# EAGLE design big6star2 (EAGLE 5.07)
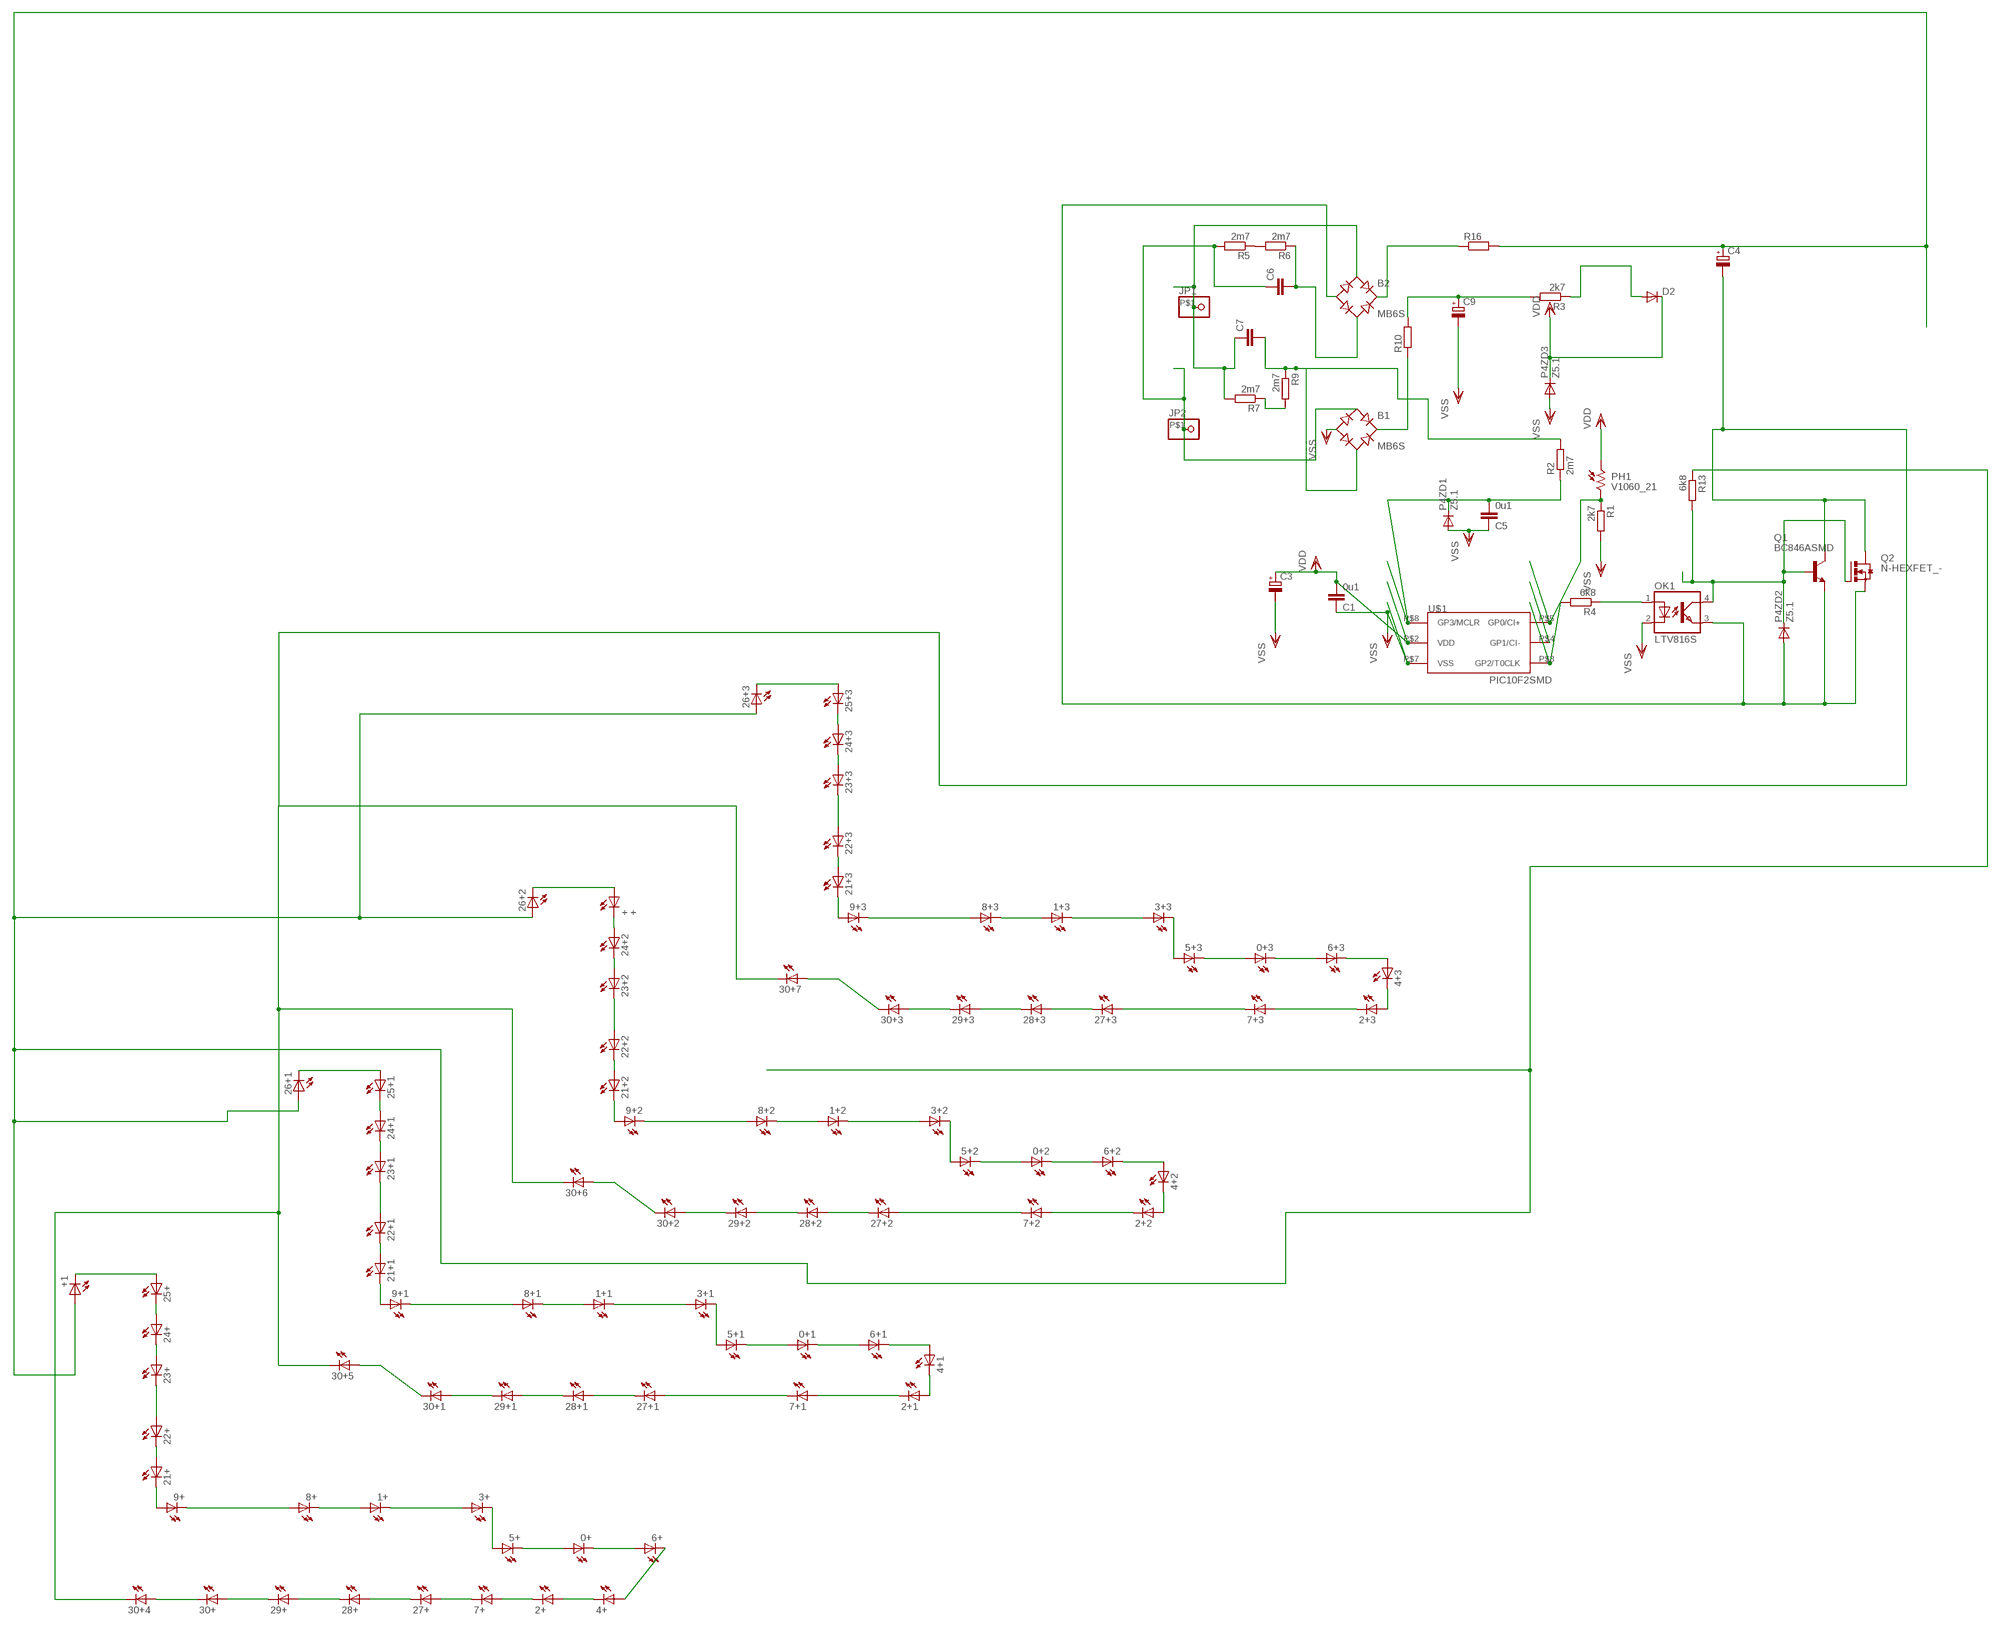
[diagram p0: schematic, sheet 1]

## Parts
0+  LED1210  [1210]
0+1  LED1210  [1210]
0+2  LED1210  [1210]
0+3  LED1210  [1210]
1+  LED1210  [1210]
1+1  LED1210  [1210]
1+2  LED1210  [1210]
1+3  LED1210  [1210]
2+  LED1210  [1210]
2+1  LED1210  [1210]
2+2  LED1210  [1210]
2+3  LED1210  [1210]
3+  LED1210  [1210]
3+1  LED1210  [1210]
3+2  LED1210  [1210]
3+3  LED1210  [1210]
4+  LED1210  [1210]
4+1  LED1210  [1210]
4+2  LED1210  [1210]
4+3  LED1210  [1210]
5+  LED1210  [1210]
5+1  LED1210  [1210]
5+2  LED1210  [1210]
5+3  LED1210  [1210]
6+  LED1210  [1210]
6+1  LED1210  [1210]
6+2  LED1210  [1210]
6+3  LED1210  [1210]
7+  LED1210  [1210]
7+1  LED1210  [1210]
7+2  LED1210  [1210]
7+3  LED1210  [1210]
8+  LED1210  [1210]
8+1  LED1210  [1210]
8+2  LED1210  [1210]
8+3  LED1210  [1210]
9+  LED1210  [1210]
9+1  LED1210  [1210]
9+2  LED1210  [1210]
9+3  LED1210  [1210]
21+  LED1210  [1210]
21+1  LED1210  [1210]
21+2  LED1210  [1210]
21+3  LED1210  [1210]
22+  LED1210  [1210]
22+1  LED1210  [1210]
22+2  LED1210  [1210]
22+3  LED1210  [1210]
23+  LED1210  [1210]
23+1  LED1210  [1210]
23+2  LED1210  [1210]
23+3  LED1210  [1210]
24+  LED1210  [1210]
24+1  LED1210  [1210]
24+2  LED1210  [1210]
24+3  LED1210  [1210]
25+  LED1210  [1210]
25+1  LED1210  [1210]
25+3  LED1210  [1210]
26+1  LED1210  [1210]
26+2  LED1210  [1210]
26+3  LED1210  [1210]
27+  LED1210  [1210]
27+1  LED1210  [1210]
27+2  LED1210  [1210]
27+3  LED1210  [1210]
28+  LED1210  [1210]
28+1  LED1210  [1210]
28+2  LED1210  [1210]
28+3  LED1210  [1210]
29+  LED1210  [1210]
29+1  LED1210  [1210]
29+2  LED1210  [1210]
29+3  LED1210  [1210]
30+  LED1210  [1210]
30+1  LED1210  [1210]
30+2  LED1210  [1210]
30+3  LED1210  [1210]
30+4  LED1210  [1210]
30+5  LED1210  [1210]
30+6  LED1210  [1210]
30+7  LED1210  [1210]
+  +  LED1210  [1210]
+1  LED1210  [1210]
B1  MB6S  [SOIC-4]
B2  MB6S  [SOIC-4]
C1  0u1  C-EUC1206  [C1206]
C3  CPOL-EUD  [PANASONIC_D]
C4  CPOL-EUSANYO_SMD_F12  [SANYO-OSCON_SMD_F12]
C5  0u1  C-EUC1206  [C1206]
C6  C-EUSMD200  [SMD200]
C7  C-EUSMD100  [SMD100]
C9  CPOL-EUD  [PANASONIC_D]
D2  DIODE-MINIMELF  [MINIMELF]
JP1  PINHD-1X1SMD  [SMD1X1]
JP2  PINHD-1X1SMD  [SMD1X1]
OK1  LTV816S  [SMD4]
P4ZD1  Z5.1  DIODE-MINIMELF  [MINIMELF]
P4ZD2  Z5.1  DIODE-MINIMELF  [MINIMELF]
P4ZD3  Z5.1  DIODE-MINIMELF  [MINIMELF]
PH1  V1060_21  [TO-5_V10]
Q1  BC846ASMD  [SOT23]
Q2  N-HEXFET_-  [TO252]
R1  2k7  R-EU_R1206  [R1206]
R2  2m7  R-EU_R1206  [R1206]
R3  2k7  R-EU_R1206  [R1206]
R4  6k8  R-EU_R1206  [R1206]
R5  2m7  R-EU_R1210  [R1210]
R6  2m7  R-EU_R1210  [R1210]
R7  2m7  R-EU_R1210  [R1210]
R9  2m7  R-EU_R1210  [R1210]
R10  R-EU_SMD15  [SMDCARB15]
R13  6k8  R-EU_R1206  [R1206]
R16  R-EU_SMD15  [SMDCARB15]
U$1  PIC10F2SMD  [DIL8SMD]

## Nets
AC1: B1.~1(AC1) C6.P$1 JP2.P$1 R5.2
AC2: B2.~1(AC1) C7.P$1 JP1.P$1 R7.2
CBIG: B2.~2(AC2) C6.P$2 R6.1
CSMALL: B1.~2(AC2) C7.P$2 R2.2 R9.1
D+: 26+1.P$1(A) 26+2.P$1(A) 26+3.P$1(A) +1.P$1(A) C4.+ R13.1 R16.P$2
DR+: C9.+ R3.2 R10.P$2
MINUS: 30+4.P$2(C) 30+5.P$2(C) 30+6.P$2(C) 30+7.P$2(C) C4.- Q1.3(C) Q2.3(D)
N$1: 30+3.P$2(C) 30+7.P$1(A)
N$2: 30+2.P$2(C) 30+6.P$1(A)
N$4: 30+1.P$2(C) 30+5.P$1(A)
N$5: 30+4.P$1(A) 30+.P$2(C)
N$6: 8+.P$1(A) 9+.P$2(C)
N$7: 29+.P$2(C) 30+.P$1(A)
N$8: 28+.P$2(C) 29+.P$1(A)
N$9: 27+.P$2(C) 28+.P$1(A)
N$10: 29+1.P$2(C) 30+1.P$1(A)
N$11: 28+1.P$2(C) 29+1.P$1(A)
N$12: 2+.P$2(C) 7+.P$1(A)
N$13: 7+.P$2(C) 27+.P$1(A)
N$14: 2+.P$1(A) 4+.P$2(C)
N$15: 4+.P$1(A) 6+.P$2(C)
N$16: 0+.P$2(C) 6+.P$1(A)
N$17: 0+.P$1(A) 5+.P$2(C)
N$18: 3+.P$2(C) 5+.P$1(A)
N$19: 1+.P$2(C) 3+.P$1(A)
N$20: 1+.P$1(A) 8+.P$2(C)
N$21: 27+1.P$2(C) 28+1.P$1(A)
N$22: 2+1.P$1(A) 4+1.P$2(C)
N$23: 9+.P$1(A) 21+.P$2(C)
N$24: 21+.P$1(A) 22+.P$2(C)
N$25: 22+.P$1(A) 23+.P$2(C)
N$26: 24+.P$1(A) 25+.P$2(C)
N$27: 25+.P$1(A) +1.P$2(C)
N$28: 23+.P$1(A) 24+.P$2(C)
N$29: 4+1.P$1(A) 6+1.P$2(C)
N$30: 0+1.P$2(C) 6+1.P$1(A)
N$31: 0+1.P$1(A) 5+1.P$2(C)
N$32: 3+1.P$2(C) 5+1.P$1(A)
N$33: 1+1.P$2(C) 3+1.P$1(A)
N$34: 1+1.P$1(A) 8+1.P$2(C)
N$35: 9+1.P$1(A) 21+1.P$2(C)
N$36: 21+1.P$1(A) 22+1.P$2(C)
N$37: 22+1.P$1(A) 23+1.P$2(C)
N$38: 25+1.P$1(A) 26+1.P$2(C)
N$39: 24+1.P$1(A) 25+1.P$2(C)
N$40: 23+1.P$1(A) 24+1.P$2(C)
N$41: 2+1.P$2(C) 7+1.P$1(A)
N$42: 7+1.P$2(C) 27+1.P$1(A)
N$43: 8+1.P$1(A) 9+1.P$2(C)
N$46: 29+2.P$2(C) 30+2.P$1(A)
N$47: 28+2.P$2(C) 29+2.P$1(A)
N$48: 27+2.P$2(C) 28+2.P$1(A)
N$49: 2+2.P$1(A) 4+2.P$2(C)
N$50: 4+2.P$1(A) 6+2.P$2(C)
N$51: 0+2.P$2(C) 6+2.P$1(A)
N$52: 0+2.P$1(A) 5+2.P$2(C)
N$53: 3+2.P$2(C) 5+2.P$1(A)
N$54: 1+2.P$2(C) 3+2.P$1(A)
N$55: 1+2.P$1(A) 8+2.P$2(C)
N$56: 9+2.P$1(A) 21+2.P$2(C)
N$57: 21+2.P$1(A) 22+2.P$2(C)
N$58: 22+2.P$1(A) 23+2.P$2(C)
N$59: 26+2.P$2(C) +.P$1(A)
N$60: 24+2.P$1(A) +.P$2(C)
N$61: 23+2.P$1(A) 24+2.P$2(C)
N$62: 2+2.P$2(C) 7+2.P$1(A)
N$63: 7+2.P$2(C) 27+2.P$1(A)
N$64: 8+2.P$1(A) 9+2.P$2(C)
N$67: 29+3.P$2(C) 30+3.P$1(A)
N$68: 28+3.P$2(C) 29+3.P$1(A)
N$69: 27+3.P$2(C) 28+3.P$1(A)
N$70: 2+3.P$1(A) 4+3.P$2(C)
N$71: 4+3.P$1(A) 6+3.P$2(C)
N$72: 0+3.P$2(C) 6+3.P$1(A)
N$73: 0+3.P$1(A) 5+3.P$2(C)
N$74: 3+3.P$2(C) 5+3.P$1(A)
N$75: 1+3.P$2(C) 3+3.P$1(A)
N$76: 1+3.P$1(A) 8+3.P$2(C)
N$77: 9+3.P$1(A) 21+3.P$2(C)
N$78: 21+3.P$1(A) 22+3.P$2(C)
N$79: 22+3.P$1(A) 23+3.P$2(C)
N$80: 25+3.P$1(A) 26+3.P$2(C)
N$81: 24+3.P$1(A) 25+3.P$2(C)
N$82: 23+3.P$1(A) 24+3.P$2(C)
N$83: 2+3.P$2(C) 7+3.P$1(A)
N$84: 7+3.P$2(C) 27+3.P$1(A)
N$85: 8+3.P$1(A) 9+3.P$2(C)
N$86: C5.2 P4ZD1.C R2.1 U$1.P$8(GP3/MCLR)
N$87: OK1.1(A) R4.1
N$88: PH1.2 R1.1 U$1.P$5(GP0/CI+)
N$89: R5.1 R6.2
N$90: R7.1 R9.2
N$91: B2.+ R16.P$1
N$92: D2.A R3.1
N$93: B2.- OK1.3(EMIT) P4ZD2.A Q1.2(E) Q2.2(S)
N$94: OK1.4(COL) P4ZD2.C Q1.1(B) Q2.1(G) R13.2
N$95: R4.2 U$1.P$3(GP2/T0CLK)
N$102: U$1.P$4(GP1/CI-)
RECDR+: B1.+ R10.P$1
VDD: C1.2 C3.+ D2.C P4ZD3.C PH1.1 U$1.P$2(VDD)
VSS: B1.- C1.1 C3.- C5.1 C9.- OK1.2(C) P4ZD1.A P4ZD3.A R1.2 U$1.P$7(VSS)

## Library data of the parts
0+ 0+1-0+3 1+ 1+1-1+3 2+ 2+1-2+3 3+ 3+1-3+3 4+ 4+1-4+3 5+ 5+1-5+3 6+ 6+1-6+3 7+ 7+1-7+3 8+ 8+1-8+3 9+ 9+1-9+3 21+ 21+1-21+3 22+ 22+1-22+3 23+ 23+1-23+3 24+ 24+1-24+3 25+ 25+1 25+3 26+1-26+3 27+ 27+1-27+3 28+ 28+1-28+3 29+ 29+1-29+3 30+ 30+1-30+7 + +1 = led(2):LED: LED
B1 B2 = rectifier:MB*S: Bridge Rectifier Source: http://www.fairchildsemi.com/ds/MB/MB6S.pdf
C1 C5-C7 = rcl:C-EU: CAPACITOR, European symbol
C3 C4 C9 = rcl-2:CPOL-EU: POLARIZED CAPACITOR, European symbol
D2 P4ZD1-P4ZD3 = diode:DIODE-: DIODE
JP1 JP2 = pinhead:PINHD-1X1: PIN HEADER
OK1 = optocoupler:LTV816: OPTO COUPLER Source: LITEON, LTV816.pdf
PH1 = photo-elements:?1060*: Sensor Street Light control
Q1 = transistor-npn:BC846*: NPN Transistor
Q2 = transistor-power:N-HEXFET_?-*: HEXFET® Power MOSFET
R1-R7 R9 R13 = rcl-2:R-EU_: RESISTOR, European symbol
R10 R16 = rcl:R-EU_: RESISTOR, European symbol
U$1 = microchip-5:PIC10F2*: uPC nW 0,25/0,5k Program Flash memory Comparator

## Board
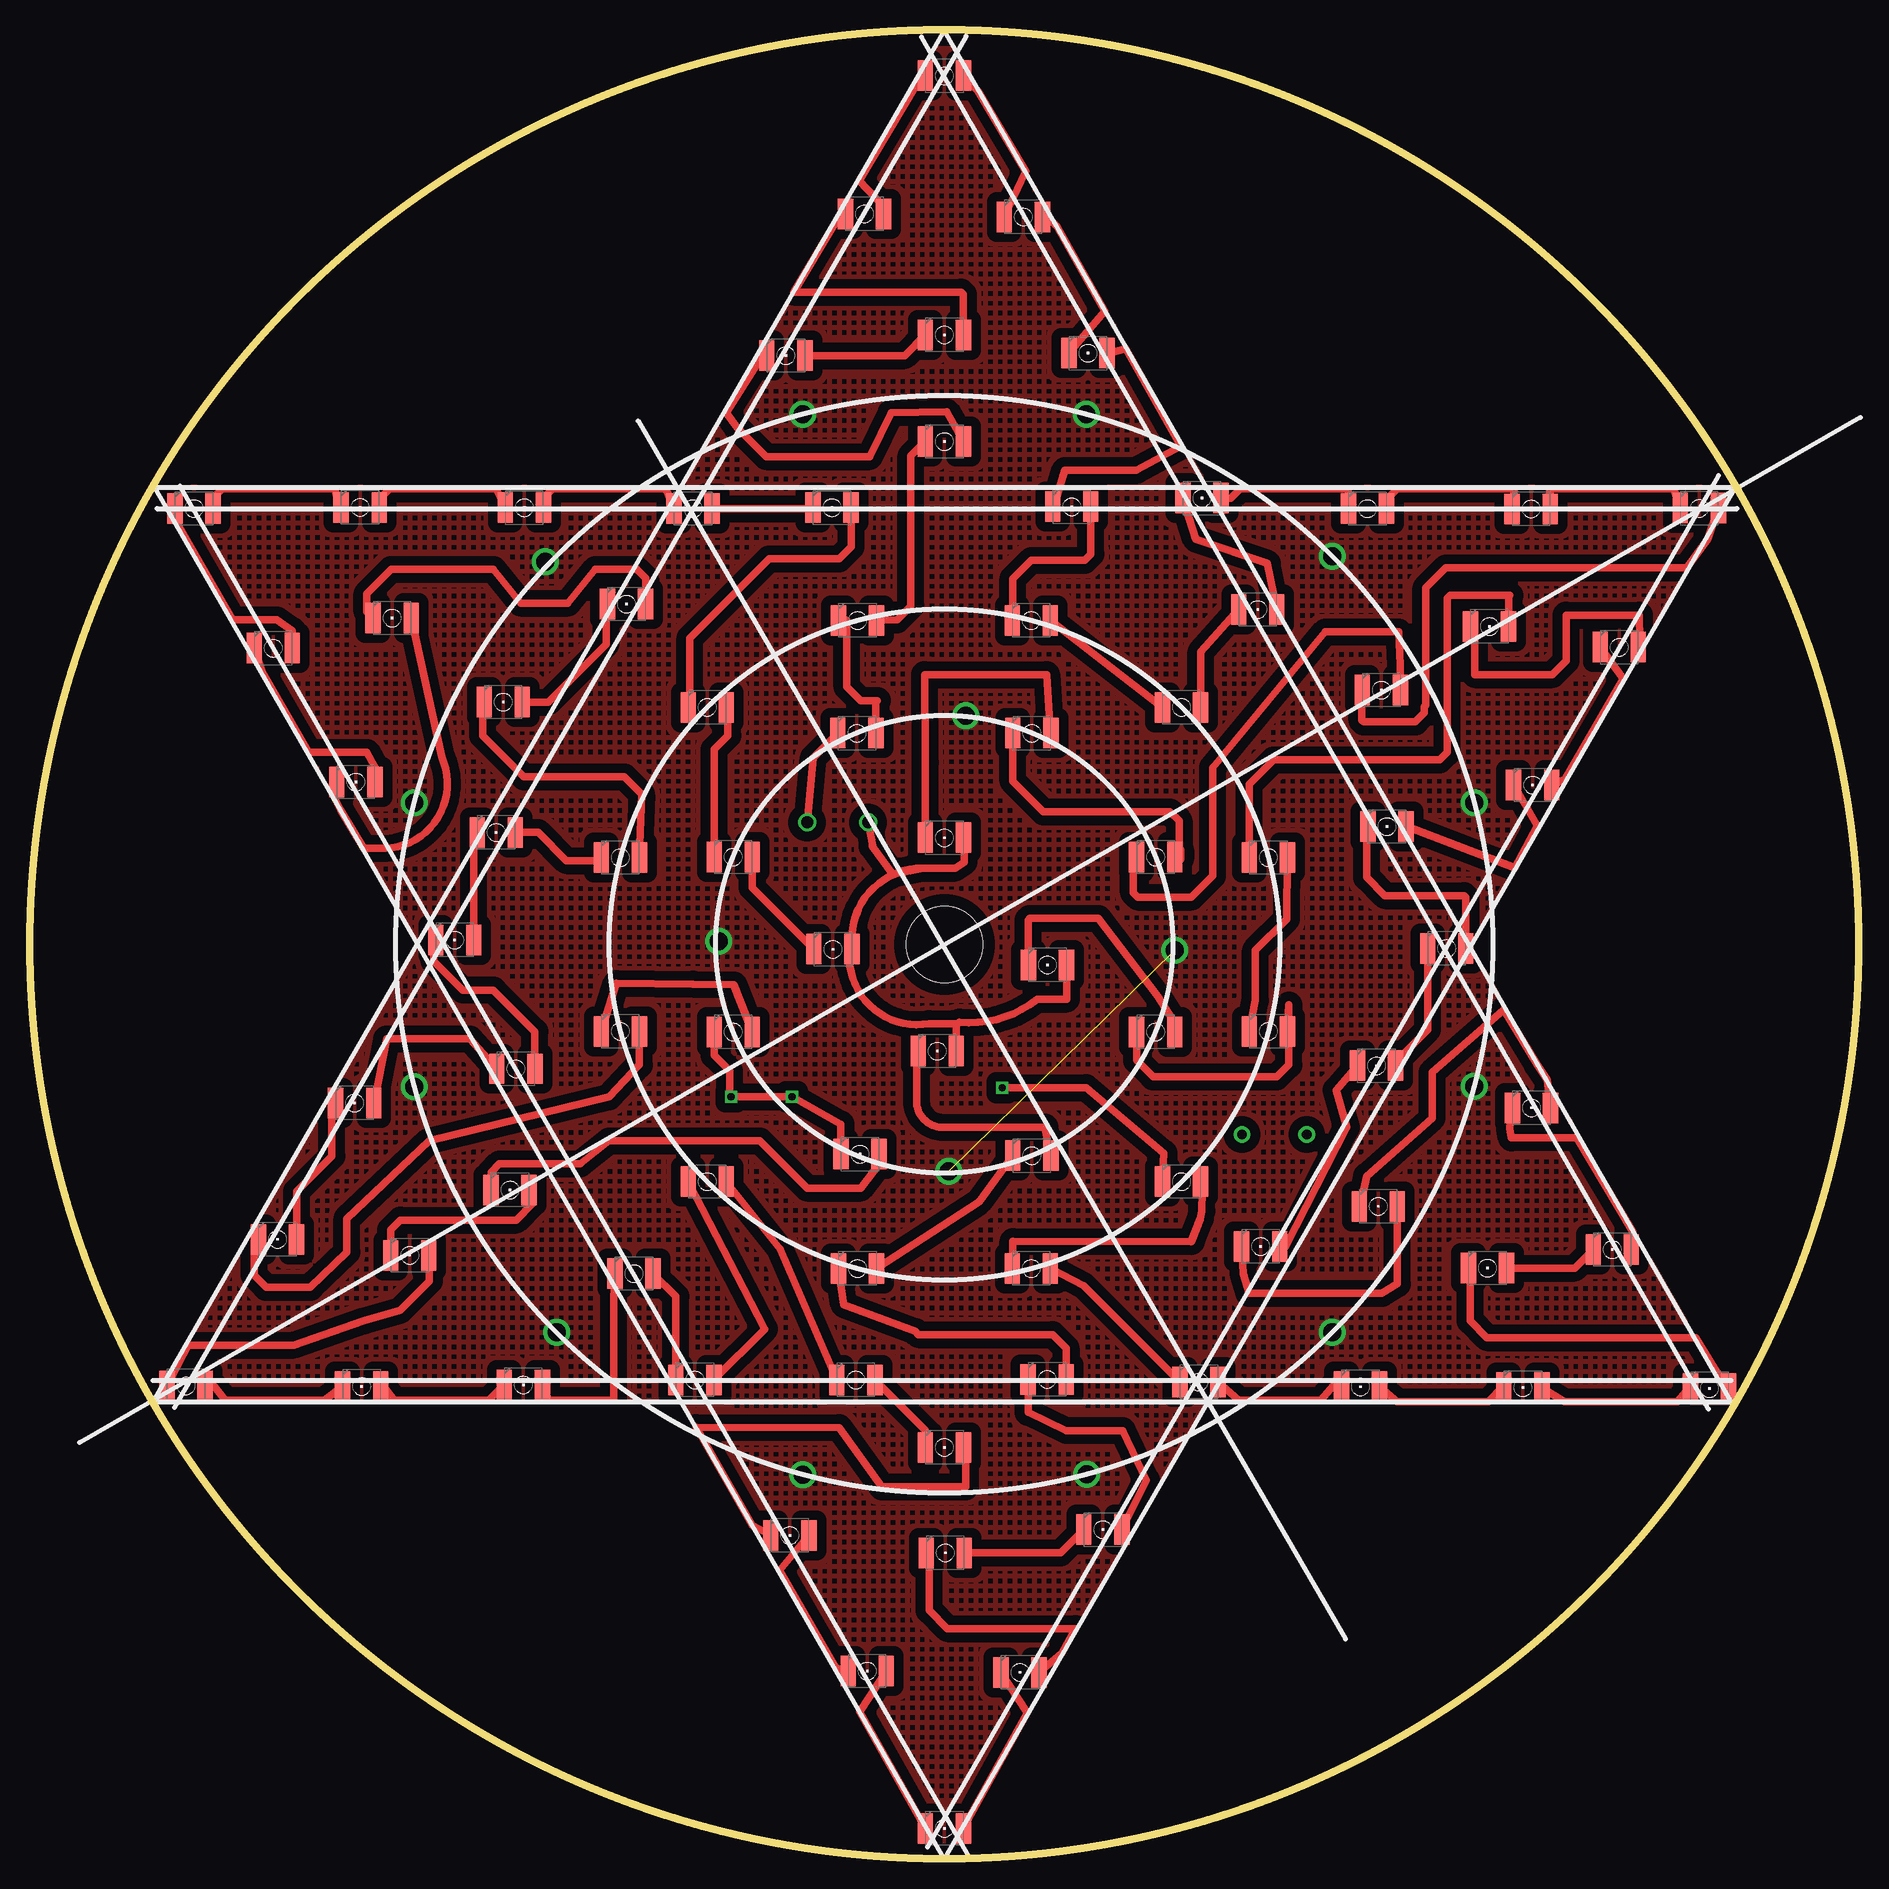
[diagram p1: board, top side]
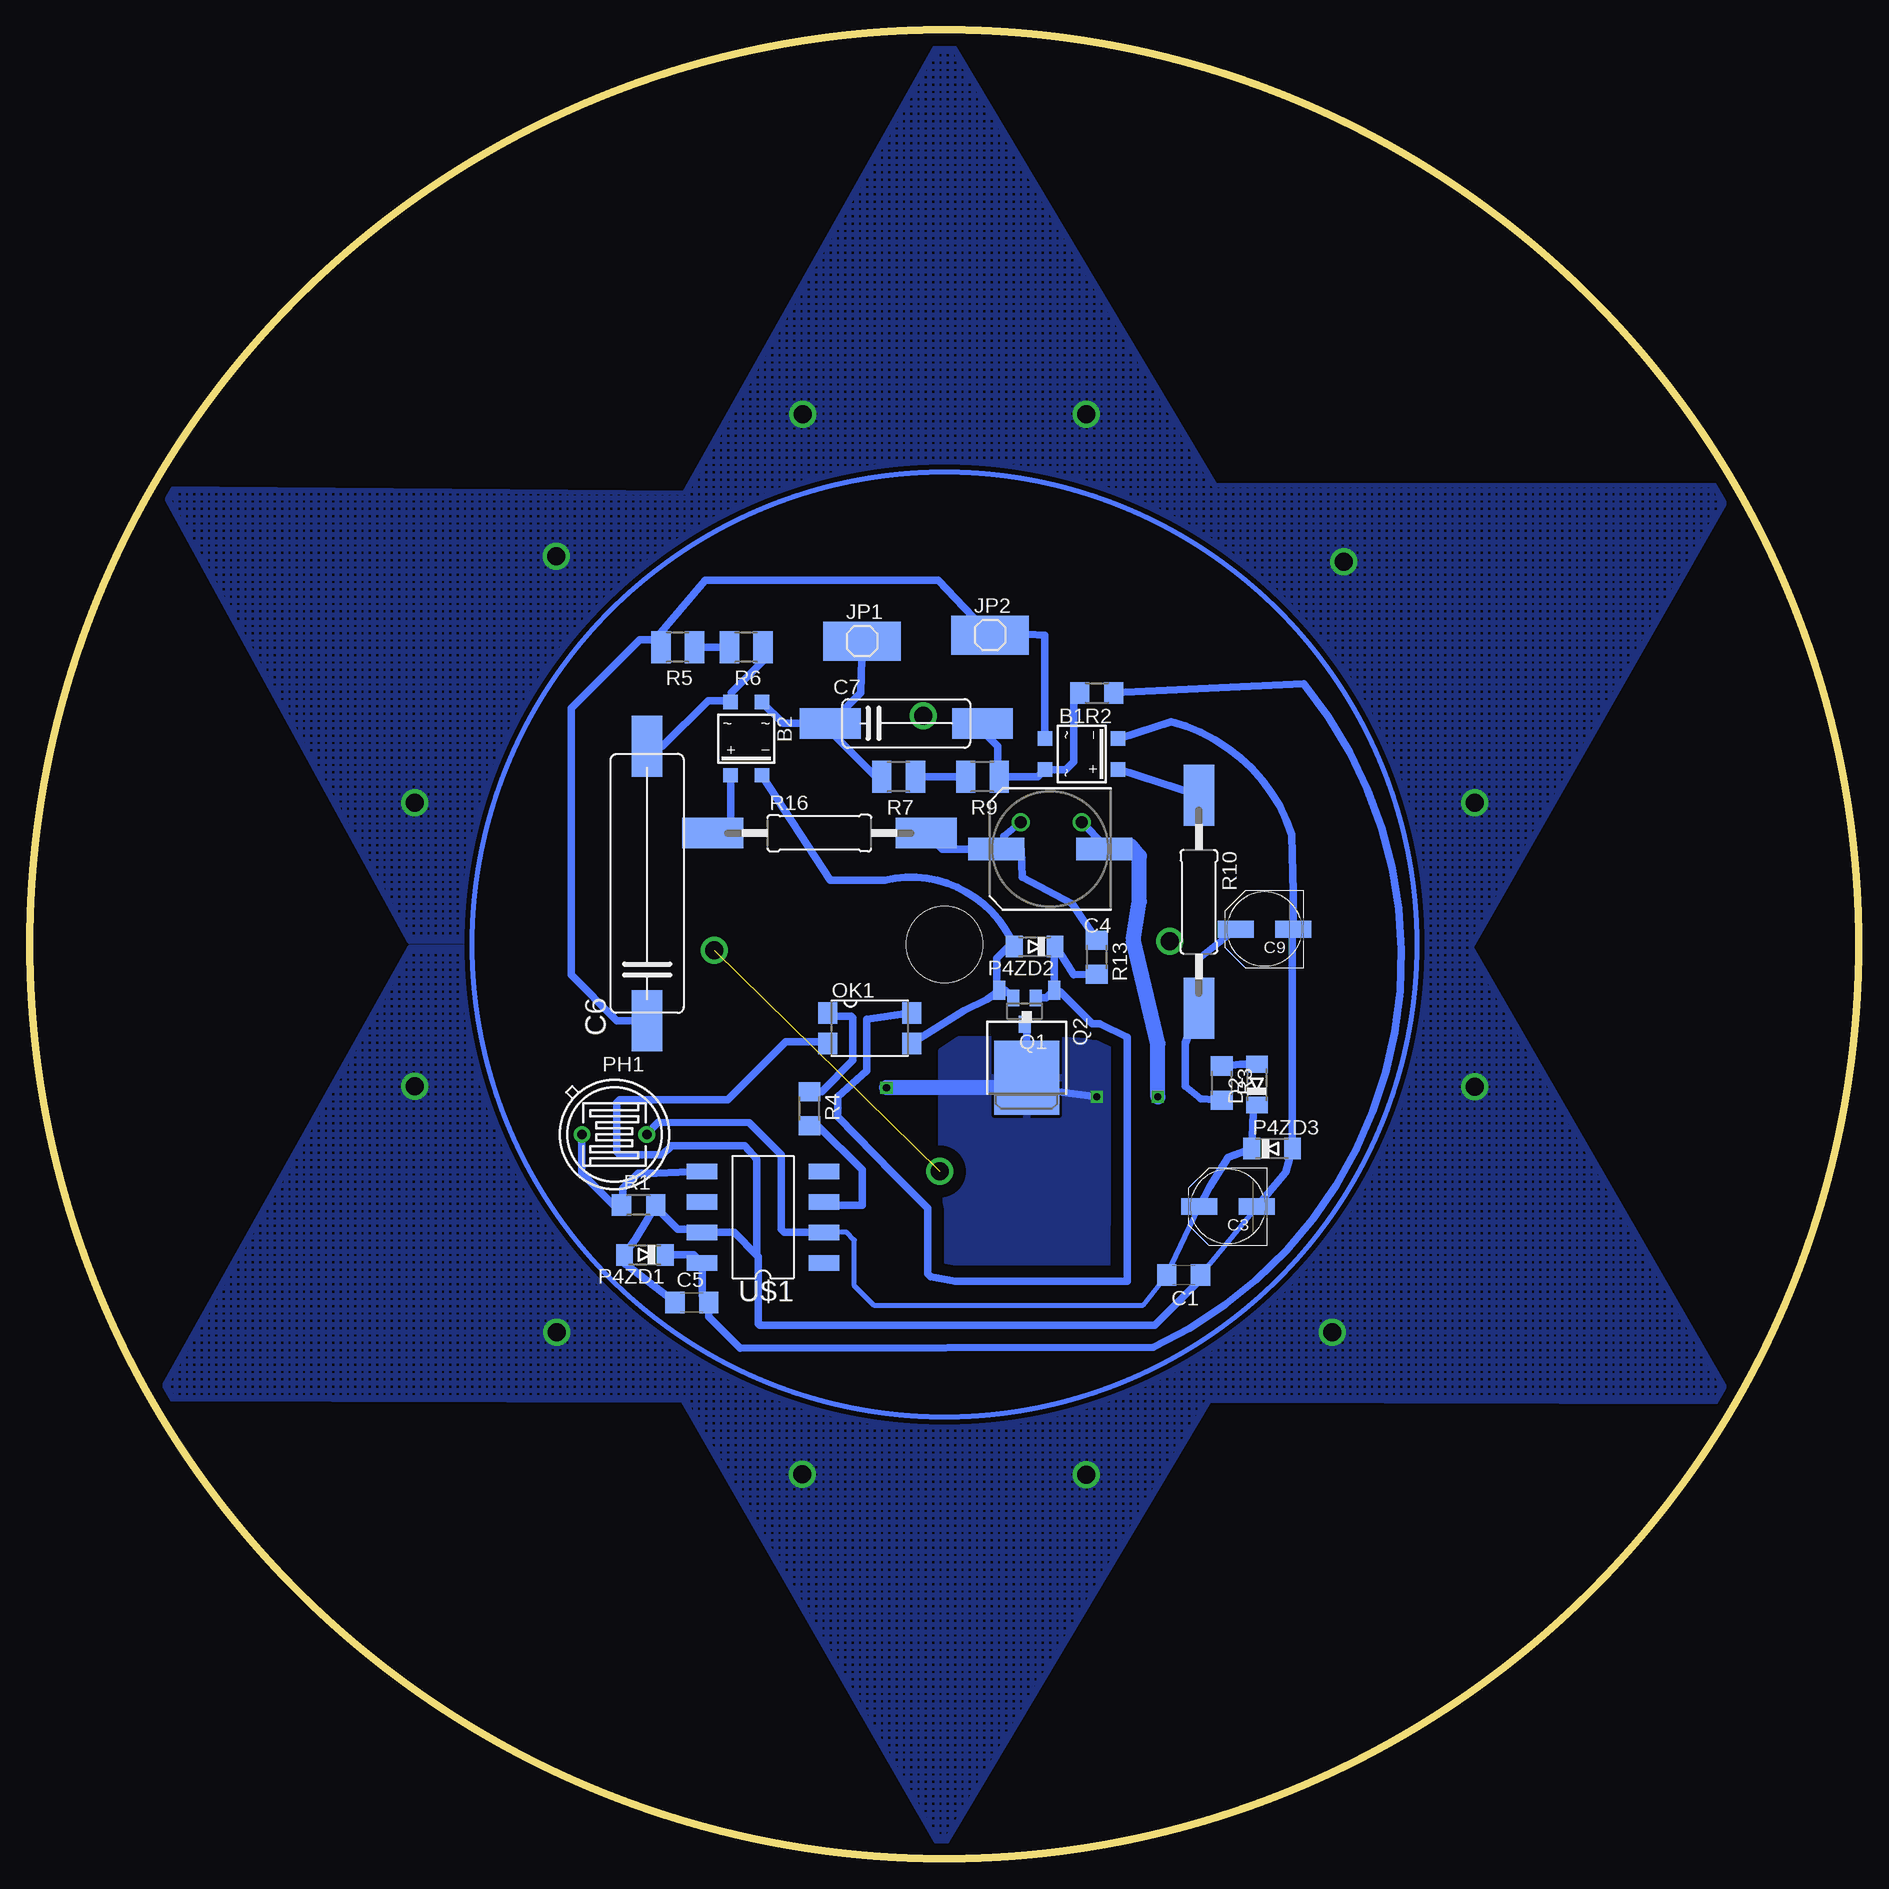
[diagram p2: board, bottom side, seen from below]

Size 152.4 x 152.4 mm. Coordinates in mm from the lower left corner, seen from the top.
Outline: circle at 76.2,76.2 radius 76.2
Copper layers (1*16): Top 0.035mm / dielectric 1.5mm / Bottom 0.035mm
Design rules "default": minimum track width 10mil, minimum drill 24mil, track to track 8mil, track to pad 8mil, pad to pad 8mil, via to via 8mil, smd to smd 8mil, copper to edge 40mil, drill to drill 8mil, minimum pad ring 10mil, minimum via ring 8mil, stop-mask expansion 4mil, vias tented up to drill 0mil, thermal gap 10mil
Holes 6.35 mm at 76.2,76.2

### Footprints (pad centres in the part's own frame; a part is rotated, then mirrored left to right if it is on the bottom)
1210 = smd 1.27 x 2.54: P$1 1.587,0; P$2 -1.587,0
SOIC-4 = smd 1.2 x 1.2: + 1.3,3.05; - -1.3,3.05; ~1 -1.3,-3.05; ~2 1.3,-3.05
C1206 = smd 1.6 x 1.8: 1 -1.4,0; 2 1.4,0
PANASONIC_D = smd 3 x 1.4: + 2.4,0; - -2.4,0
SANYO-OSCON_SMD_F12 = smd 4.7 x 1.9: + 4.5,0; - -4.5,0
SMD200 = smd 5.08 x 2.54: P$1 -10.16,0; P$2 12.7,0
SMD100 = smd 5.08 x 2.54: P$1 -6.35,0; P$2 6.35,0
MINIMELF = smd 1.4 x 1.8: A 1.7,0; C -1.7,0
SMD1X1 = smd 6.452 x 3.251: P$1 0,0
SMD4 = smd 1.78 x 1.55: 1 -1.27,-3.5; 2 1.27,-3.5; 3 1.27,3.5; 4 -1.27,3.5
TO-5_V10 = drill 0.8 pad 1.4 round: 1 -2.7,0; 2 2.7,0
SOT23 = smd 1 x 1.4: 1 -0.95,-1.1; 2 0.95,-1.1; 3 0,1.1
TO252 = smd 1 x 1.6: 1 -2.28,-3.53; 2 2.28,-3.53 | smd 5.4 x 6.2: 3 0,3.77
R1206 = smd 1.6 x 1.803: 1 -1.422,0; 2 1.422,0
R1210 = smd 1.6 x 2.7: 1 -1.4,0; 2 1.4,0
SMDCARB15 = smd 5.08 x 2.54: P$1 -8.89,0; P$2 8.89,0
DIL8SMD = smd 1.27 x 2.54: P$1 -3.81,-5.08; P$2 -1.27,-5.08; P$3 1.27,-5.08; P$4 3.81,-5.08; P$5 3.81,5.08; P$6 1.27,5.08; P$7 -1.27,5.08; P$8 -3.81,5.08

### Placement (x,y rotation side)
0+  68.82,39.91 0 top
0+1  112.36,54.38 0 top
0+2  86.82,112.67 0 top
0+3  49.71,104.56 0 top
1+  69.77,15.65 0 top
1+1  118.06,75.87 0 top
1+2  102.31,104.11 0 top
1+3  20.28,100.89 0 top
2+  50.33,48.77 0 top
2+1  121.46,49.23 0 top
2+2  76.2,148.59 0 top
2+3  38.85,85.54 0 top
3+  63.32,26.95 0 top
3+1  112.21,66.09 0 top
3+2  95.96,95.96 0 top
3+3  27.15,89.74 0 top
4+  55.41,39.91 0 top
4+1  131.85,50.77 0 top
4+2  82.78,136.83 0 top
4+3  49.2,83.44 0 top
5+  76.2,34.29 0 top
5+1  102.56,51.04 0 top
5+2  83.44,103.2 0 top
5+3  30.18,103.4 0 top
6+  56.44,56.44 0 top
6+1  125.12,62.59 0 top
6+2  88.16,125.48 0 top
6+3  39.43,96.4 0 top
7+  41.11,39.5 0 top
7+1  139.95,39.19 0 top
7+2  69.55,137.08 0 top
7+3  35.39,76.57 0 top
8+  76.2,2.54 0 top
8+1  113.08,86.03 0 top
8+2  97.66,113.39 0 top
8+3  13.67,112.53 0 top
9+  82.5,15.54 0 top
9+1  125.22,89.48 0 top
9+2  111.46,112.52 0 top
9+3  27.51,112.62 0 top
21+  76.28,25.5 0 top
21+1  132.44,100.97 0 top
21+2  125.09,112.5 0 top
21+3  41.2,112.6 0 top
22+  89.41,27.43 0 top
22+1  121.63,102.7 0 top
22+2  139.12,112.55 0 top
22+3  55.25,112.52 0 top
23+  84.76,39.96 0 top
23+1  103.2,83.44 0 top
23+2  112.62,97.4 0 top
23+3  66.84,112.6 0 top
24+  68.96,49.2 0 top
24+1  103.2,68.96 0 top
24+2  93.8,83.49 0 top
24+3  56.44,95.96 0 top
25+  83.49,58.6 0 top
25+1  93.8,68.91 0 top
25+3  58.6,83.49 0 top
26+1  84.79,74.5 0 top
26+2  76.2,85.09 0 top
26+3  66.91,75.8 0 top
27+  27.64,39.37 0 top
27+1  124.41,39.27 0 top
27+2  76.2,127 0 top
27+3  40.49,65.84 0 top
28+  13,39.42 0 top
28+1  110.87,39.34 0 top
28+2  62.99,125.27 0 top
28+3  27.05,62.99 0 top
29+  31.65,50.29 0 top
29+1  97.41,39.74 0 top
29+2  76.2,118.11 0 top
29+3  20.63,51.63 0 top
30+  40.01,55.74 0 top
30+1  83.44,49.2 0 top
30+2  68.96,103.2 0 top
30+3  49.2,68.96 0 top
30+4  69.16,58.72 0 top
30+5  95.96,56.44 0 top
30+6  68.91,93.8 0 top
30+7  58.6,68.91 0 top
+  83.49,93.8 0 top
+1  75.6,67.31 0 top
B1  64.77,92.08 270 bottom
B2  92.71,93.34 180 bottom
C1  56.26,48.64 180 bottom
C3  52.58,54.36 180 bottom
C4  67.38,84.14 180 bottom
C5  97.25,46.36 0 bottom
C6  100.97,80.01 90 bottom
C7  79.38,94.61 0 bottom
C9  49.53,77.47 180 bottom
D2  50.16,64.52 90 bottom
JP1  83.06,101.47 0 bottom
JP2  72.39,101.98 0 bottom
OK1  82.42,69.22 270 bottom
P4ZD1  101.16,50.33 180 bottom
P4ZD2  68.68,76.02 180 bottom
P4ZD3  48.9,59.18 0 bottom
PH1  103.69,60.36 180 bottom
Q1  69.52,70.64 180 bottom
Q2  69.34,68.86 180 bottom
R1  101.69,54.48 0 bottom
R2  63.5,97.16 180 bottom
R3  53.09,64.64 270 bottom
R4  87.45,62.51 270 bottom
R5  98.42,100.97 180 bottom
R6  92.71,100.97 180 bottom
R7  80.01,90.17 180 bottom
R9  73.03,90.17 180 bottom
R10  54.99,79.76 270 bottom
R13  63.5,75.13 270 bottom
R16  86.61,85.47 0 bottom
U$1  91.31,53.47 90 bottom

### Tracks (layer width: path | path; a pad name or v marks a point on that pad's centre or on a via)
AC1
  Bottom 0.61: B1.~1 67.82,101.98 69.98,102.11 JP2.P$1 76.71,106.55 96.14,106.55 100.33,101.6 | 100.33,101.6 100.33,101.47 R5.2 | C6.P$1 103.5,69.85 107.31,73.66 107.31,95.89 101.6,101.6 100.33,101.6
AC2
  Bottom 0.61: R7.2 81.92,90.17 86.36,94.61 C7.P$1 | JP1.P$1 83.19,97.16 C7.P$1 | C7.P$1 89.63,94.61 B2.~1
CBIG
  Bottom 0.61: R6.1 91.31,99.83 93.98,97.16 93.98,96.42 B2.~2 94.14,96.52 95.89,96.52 99.69,92.71 C6.P$2
CSMALL
  Bottom 0.61: R2.2 65.41,96.67 65.41,91.44 66.07,90.78 B1.~2 68.42,90.17 R9.1 71.75,90.3 71.75,92.71 73.03,93.98 C7.P$2
D+  (via drill 1 pad 1.27)
  Top 0.61: 74.42,82.55 arc94 68.5,76.37 26+3.P$1 68.33,75.63 68.33,74.42 arc93 74.93,69.6 76.96,69.6 77.31,69.62 77.19,69.47 | 74.42,82.55 77.09,82.55 77.85,83.06 77.85,85.03 26+2.P$1 | 77.19,69.47 +1.P$1 | 26+1.P$1 86.38,71.64 83.95,71.63 arc-44 77.44,69.72 77.19,69.47 | 74.42,82.55 71.88,82.04 70.18,84.38 70.23,84.42 v69.85,86.36
  Bottom 0.61: R13.1 65.53,79.6 69.72,81.79 69.79,84.14 71.25,84.14 | 71.25,84.14 C4.+ 76.39,84.14 R16.P$2 | v69.85,86.36 71.25,85.22 71.25,84.14
DR+
  Bottom 0.61: R3.2 54.84,63.35 56.13,64.39 56.13,67.94 R10.P$2 54.98,75.06 C9.+
MINUS  (via drill 0.6, 1 pad 1.27)
  Top 0.61: 30+6.P$2 65.28,91.76 v64.77,86.36 | 30+5.P$2 94.49,58.8 88.01,64.26 v81.03,64.26 | 30+4.P$2 67.58,61.23 v63.5,63.5 v58.42,63.5 58.29,63.5 58.29,65.66 57.01,66.94 30+7.P$2
  Bottom 0.61: 60.64,84.4 C4.- 62.88,84.47 v64.77,86.36 | Q2.3 70.17,64.26 | v63.5,63.5 68.39,64.14 Q2.3 | Q1.3 69.34,69.54 Q2.3
  Bottom 1.27: 60.64,84.4 59.94,83.57 59.94,79.76 60.45,76.58 58.42,67.94 v58.42,63.5 | 70.17,64.26 v81.03,64.26
  pour Bottom (isolate 1.016): 67.18,68.25 74.98,68.25 76.41,67.31 76.41,49.48 62.66,49.33 62.64,56.21 62.64,68.02
N$1
  Top 0.61: 30+3.P$2 48.87,72.95 55.24,72.9 58.66,72.82 30+7.P$1
N$2
  Top 0.61: 30+2.P$2 68.07,103.21 68.07,97.66 69.22,96.52 70.61,96.52 70.5,96.41 30+6.P$1
N$4
  Top 0.61: 30+1.P$2 81.92,51.45 96.77,51.44 97.54,53.34 97.66,53.98 97.68,55.64 30+5.P$1
N$5
  Top 0.61: 30+.P$2 38.42,57.21 39.12,57.91 45.85,57.91 48.26,59.82 60.83,59.82 64.77,55.88 69.22,55.88 70.99,58.17 70.99,58.48 30+4.P$1
N$6
  Top 0.61: 9+.P$2 83.12,12.17 8+.P$1
N$7
  Top 0.61: 29+.P$2 30.06,52.41 30.86,53.21 40.51,53.21 41.91,54.61 41.91,55.43 30+.P$1
N$8
  Top 0.61: 28+.P$2 12.31,41.13 13.21,42.8 21.97,42.8 27.81,44.83 30.86,45.72 33.27,48.13 33.27,50.25 29+.P$1
N$9
  Top 0.61: 27+.P$2 24.51,38.23 16.26,38.23 15.37,39.37 15.11,39.62 14.8,39.62 28+.P$1
N$10
  Top 0.61: 29+1.P$2 87.82,47.75 30+1.P$1
N$11
  Top 0.61: 28+1.P$2 108.89,39.74 107.57,38.23 100.71,38.23 29+1.P$1
N$12
  Top 0.61: 2+.P$2 48.64,46.61 48.64,38.23 43.22,38.26 7+.P$1
N$13
  Top 0.61: 7+.P$2 38.23,38.23 30.35,38.23 29.35,39.5 27+.P$1
N$14
  Top 0.61: 4+.P$2 53.82,46.86 2+.P$1
N$15
  Top 0.61: 6+.P$2 61.22,44.13 4+.P$1
N$16
  Top 0.61: 0+.P$2 62.53,50.8 6+.P$1
N$17
  Top 0.61: 5+.P$2 74.61,35.71 0+.P$1
N$18
  Top 0.61: 3+.P$2 60.2,27.81 55.51,35.95 67.44,35.94 70.99,30.99 77.98,30.99 77.98,34.1 5+.P$1
N$19
  Top 0.61: 1+.P$2 67.18,15.88 62.47,24.05 3+.P$1
N$20
  Top 0.61: 8+.P$2 69.15,12.27 1+.P$1
N$21
  Top 0.61: 27+1.P$2 122.75,39.34 121.54,38.1 113.92,38.1 28+1.P$1
N$22
  Top 0.61: 4+1.P$2 128.72,49.23 2+1.P$1
N$23
  Top 0.61: 21+.P$2 74.93,25.26 74.93,20.7 76.45,19.18 87.12,19.18 85.99,17.13 9+.P$1
N$24
  Top 0.61: 22+.P$2 85.89,25.5 21+.P$1
N$25
  Top 0.61: 23+.P$2 83.19,39.95 83.19,37.21 86.36,35.69 91.06,35.69 93.03,31.56 22+.P$1
N$26
  Top 0.61: 25+.P$2 79.09,54.77 24+.P$1
N$27
  Top 0.61: +1.P$2 73.91,67.21 73.91,62.74 arc82 76.2,60.96 82.17,60.96 84.57,60.97 25+.P$1
N$28
  Top 0.61: 24+.P$2 67.82,46.17 73.79,43.94 74.04,43.69 85.22,43.69 86.35,42.56 23+.P$1
N$29
  Top 0.61: 6+1.P$2 123.44,62.5 123.32,60.83 123.44,60.07 128.91,60.07 133.57,52.23 4+1.P$1
N$30
  Top 0.61: 0+1.P$2 110.87,54.48 111.38,56.9 116.84,61.72 116.84,65.53 122.81,70.74 125.6,66.17 126.45,64.94 6+1.P$1
N$31
  Top 0.61: 5+1.P$2 101.09,48.77 101.6,47.12 112.65,47.12 113.95,47.91 0+1.P$1
N$32
  Top 0.61: 3+1.P$2 108.84,64.05 109.73,60.96 104.63,51.04 5+1.P$1
N$33
  Top 0.61: 1+1.P$2 116.46,75.86 116.46,69.09 113.8,66.43 3+1.P$1
N$34
  Top 0.61: 8+1.P$2 111.38,85.92 111.38,81.79 112.9,80.26 119.51,80.26 119.65,80.12 1+1.P$1
N$35
  Top 0.61: 21+1.P$2 132.78,98.32 127.89,89.92 9+1.P$1
N$36
  Top 0.61: 22+1.P$2 120.4,102.35 120.4,98.68 126.87,98.68 128.02,99.82 128.02,103.63 134.11,103.63 134.15,101.64 21+1.P$1
N$37
  Top 0.61: 23+1.P$2 101.6,83.55 101.6,89.53 103.63,91.57 117.47,91.57 118.11,92.2 118.11,105.03 118.36,105.28 123.32,105.28 123.22,105.18 22+1.P$1
N$38
  Top 0.61: 26+1.P$2 83.19,74.52 83.19,78.23 83.31,78.36 89.03,78.36 93.98,71.88 95.5,69.47 95.39,69.36 25+1.P$1
N$39
  Top 0.61: 24+1.P$1 104.9,71.16 104.9,66.17 103.89,65.15 93.6,65.15 92.22,66.53 25+1.P$2
N$40
  Top 0.61: 24+1.P$2 102.11,71.54 102.11,75.69 104.72,78.3 23+1.P$1
N$41
  Top 0.61: 2+1.P$2 119.89,49.25 119.89,49.28 120.02,49.15 120.02,44.83 121.41,43.43 138.81,43.43 140.4,40.83 7+1.P$1
N$42
  Top 0.61: 7+1.P$2 138.29,39.27 137.29,38.1 127.89,38.1 27+1.P$1
N$43
  Top 0.61: 9+1.P$2 125.6,86.11 123.74,82.6 8+1.P$1
N$46
  Top 0.61: 29+2.P$2 73.41,116.9 73.41,104.39 72.26,103.25 30+2.P$1
N$47
  Top 0.61: 28+2.P$2 60.71,124.7 58.04,120.52 58.93,119.25 61.34,116.84 69.98,116.84 71.75,120.52 76.39,120.59 29+2.P$1
N$48
  Top 0.61: 27+2.P$2 72.89,125.27 28+2.P$1
N$49
  Top 0.61: 4+2.P$2 83,140.61 78.99,147.32 77.79,148.53 2+2.P$1
N$50
  Top 0.61: 6+2.P$2 89.57,128.96 85.6,136.02 84.78,136.83 4+2.P$1
N$51
  Top 0.61: 0+2.P$2 85.34,112.79 86.23,115.7 92.2,115.7 95.89,117.73 91.31,125.86 89.92,125.48 6+2.P$1
N$52
  Top 0.61: 5+2.P$2 81.92,103.26 81.92,106.68 83.44,108.2 87.88,108.2 88.41,108.72 0+2.P$1
N$53
  Top 0.61: 5+2.P$1 3+2.P$2
N$54
  Top 0.61: 1+2.P$2 97.57,100.58 3+2.P$1
N$55
  Top 0.61: 8+2.P$2 97.16,109.98 103.12,107.95 1+2.P$1
N$56
  Top 0.61: 9+2.P$1 113.04,113.3 113.92,114.17 123.7,114.17 21+2.P$2
N$57
  Top 0.61: 21+2.P$1 126.68,113.73 126.62,114.17 136.91,114.17 137.03,114.05 22+2.P$2
N$58
  Top 0.61: 23+2.P$2 111,97.37 111,94.87 111.12,94.74 115.44,94.74 116.2,95.5 116.2,96.01 116.33,96.14 116.33,105.92 117.98,107.57 138.05,107.57 139.81,109.97 22+2.P$1
N$59
  Top 0.61: 26+2.P$2 74.61,91.38 74.55,98.68 84.71,98.68 84.96,94.61 85.22,94.36 85.22,93.94 +.P$1
N$60
  Top 0.61: +.P$2 81.9,89.8 84.45,87.25 95,87.25 95.76,86.49 95.76,84.2 95.89,84.07 95.89,83.31 95.76,83.19 95.69,83.19 24+2.P$1
N$61
  Top 0.61: 24+2.P$2 91.95,83.22 91.95,80.52 92.33,80.14 96.77,80.14 98.55,81.92 98.55,90.93 107.95,102.23 114.05,102.23 114.21,99.47 23+2.P$1
N$62
  Top 0.61: 2+2.P$2 73.91,147.89 69.09,139.83 71.13,137.68 7+2.P$1
N$63
  Top 0.61: 7+2.P$2 67.94,137.07 67.86,137.07 67.06,136.27 63.63,130.56 77.6,130.56 77.79,130.37 27+2.P$1
N$64
  Top 0.61: 8+2.P$1 100.05,113.39 100.84,114.17 109.86,114.17 9+2.P$2
N$67
  Top 0.61: 30+3.P$1 50.79,66.15 48.26,63.5 33.27,59.82 26.42,53.34 26.42,50.55 23.37,47.62 19.68,47.62 18.67,48.64 18.67,50.93 18.8,51.05 18.8,51.38 29+3.P$2
N$68
  Top 0.61: 29+3.P$1 22.22,55.62 25.15,58.55 25.15,62.67 28+3.P$2
N$69
  Top 0.61: 28+3.P$1 28.7,62.99 29.72,68.33 36.66,68.33 27+3.P$2
N$70
  Top 0.61: 2+3.P$1 42.35,85.54 44.7,83.19 47.49,83.19 4+3.P$2
N$71
  Top 0.61: 4+3.P$1 50.97,88.73 49.53,90.17 41.15,90.17 37.72,93.6 37.72,96.27 6+3.P$2
N$72
  Top 0.61: 6+3.P$1 43.19,96.4 48.01,101.22 48.01,104.45 0+3.P$2
N$73
  Top 0.61: 0+3.P$1 51.29,106.69 50.55,107.44 47.12,107.44 44.83,104.65 40.89,104.65 38.61,107.44 30.1,107.44 28.07,105.41 28.07,103.92 5+3.P$2
N$74
  Top 0.61: 5+3.P$1 34.3,91.83 arc-118 29.08,84.2 27.81,84.2 25.91,87.38 25.4,88.39 25.4,89.57 3+3.P$2
N$75
  Top 0.61: 3+3.P$1 28.74,91.02 28.07,92.2 23.24,92.2 19.3,99 1+3.P$2
N$76
  Top 0.61: 1+3.P$1 21.86,102.34 20.57,103.25 16.89,103.25 11.94,111.89 11.94,112.39 8+3.P$2
N$77
  Top 0.61: 9+3.P$1 29.1,113.3 29.97,114.17 38.86,114.17 39.59,112.62 21+3.P$2
N$78
  Top 0.61: 22+3.P$2 53.59,112.6 53.09,113.92 52.83,114.17 43.56,114.17 42.79,113.4 21+3.P$1
N$79
  Top 0.61: 23+3.P$2 65.17,112.52 22+3.P$1
N$80
  Top 0.61: 25+3.P$1 60.19,80.94 26+3.P$2
N$81
  Top 0.61: 25+3.P$2 57.01,92.44 58.17,93.6 58.17,95.82 24+3.P$1
N$82
  Top 0.61: 24+3.P$2 54.99,96.1 54.99,101.73 61.59,108.33 67.44,108.33 68.42,109.32 23+3.P$1
N$83
  Top 0.61: 7+3.P$1 36.98,85.25 2+3.P$2
N$84
  Top 0.61: 27+3.P$1 42.08,68.92 38.61,72.39 36.07,72.39 33.66,74.8 33.66,76.43 7+3.P$2
N$85
  Top 0.61: 8+3.P$1 15.26,113.43 16,114.17 25.4,114.17 25.83,112.53 9+3.P$2
N$86
  Bottom 0.61: R2.1 46.27,97.92 arc104 58.78,42.62 93.22,42.55 95.85,45.18 C5.2 96.39,46.91 U$1.P$8 97.07,50.33 P4ZD1.C
N$87
  Bottom 0.61: OK1.1 85.67,70.23 83.95,70.23 83.82,70.1 83.82,66.55 86.44,63.93 R4.1
N$88
  Bottom 0.61: U$1.P$5 100.2,57.15 101.73,57.15 103,55.88 103,54.59 R1.1 103.75,54.48 106.43,57.15 106.43,60.33 PH1.2
N$89
  Bottom 0.61: R6.2 96.52,100.97 97.16,100.33 97.16,100.83 R5.1
N$90
  Bottom 0.61: R9.2 R7.1
N$91
  Bottom 0.61: B2.+ 94.01,86.39 R16.P$1
N$92
  Bottom 0.61: D2.A 51.54,66.22 R3.1
N$93
  Bottom 0.61: Q2.2 71.83,72.6 71.83,75.06 70.87,76.02 P4ZD2.A arc-81 81.15,81.53 85.72,81.53 B2.- | Q2.2 71.12,72.39 Q1.2 | OK1.3 74.61,70.68 72.64,71.63 71.75,72.26 Q2.2
N$94
  Bottom 0.61: Q1.1 67.71,71.74 Q2.1 | OK1.4 82.68,69.98 82.68,65.66 85.09,63.5 85.09,61.85 80.52,57.15 77.6,54.23 77.6,48.77 77.34,48.51 75.31,48.13 60.96,48.13 60.96,68.45 63.25,69.6 63.88,69.6 66.55,72.26 66.94,72.26 Q2.1 | R13.2 65.41,73.66 arc-7 P4ZD2.C 67.06,76.02 Q2.1
N$95
  Bottom 0.61: U$1.P$3 85.98,54.48 83.06,54.48 83.06,57.4 86.74,61.08 R4.2
RECDR+
  Bottom 0.61: R10.P$1 61.69,90.81 B1.+
SINK  (via drill 1.5)  (1 unrouted)
  other vias: 88.05,32.03 108.52,43.87 42.93,108.08 120.36,64.38 32.02,64.36 43.89,43.87 64.39,32 32,88.01 88.01,120.4 77.98,95.25 95.38,75.69 76.58,57.28 57.4,76.45 64.39,120.4 120.36,88.03 108.54,108.55
  pour Bottom (isolate 0.406, hatched): 120.78,75.95 141.86,38.35 98.04,38.23 76.45,0.64 54.1,38.23 10.41,38.1 32.26,75.95 10.29,114.43 53.59,114.43 76.2,152.4 97.92,113.79 141.48,114.17 120.78,76.45 115.95,76.45 arc131 49.15,105.03 arc37 37.21,83.19 arc73 59.44,40.39 arc113 115.82,75.95
  pour Top (isolate 0.813, hatched): 32.44,76 10.41,38.1 54.2,38.15 76.2,0 98.15,38.13 141.88,38 120.02,76.05 142.16,114.33 98.15,114.3 76.2,152.4 54.23,114.3 10.49,114.3
VDD
  Bottom 0.406: C3.+ C1.2 59.69,46.1 82.04,46.1 83.69,47.75 83.69,51.56 84.33,52.2 U$1.P$2
  Bottom 0.61: C3.+ 54.1,56.01 52.56,58.48 P4ZD3.C 50.47,62.13 D2.C | U$1.P$2 89.53,52.2 89.79,52.45 89.79,58.67 92.46,61.34 100.04,61.38 PH1.1
VSS
  Bottom 0.406: C3.- C1.1
  Bottom 0.61: C3.- 47.77,57.22 P4ZD3.A 47.2,77.41 C9.- 47.12,80.52 47.24,85.34 arc-57 57.28,94.74 61.56,93.38 B1.- | 91.82,50.29 91.69,50.16 91.69,44.58 91.57,44.45 58.67,44.45 54.86,48.26 C1.1 | 91.82,50.29 93.73,52.2 U$1.P$7 96.65,52.45 98.42,52.45 100.27,54.29 R1.2 arc7 P4ZD1.A arc-88 102.74,49.53 C5.1 | OK1.2 86.05,68.07 89.41,68.07 94.23,63.25 103.25,63.25 103.5,62.99 103.5,58.93 103.25,58.67 99.69,58.67 98.93,59.44 92.84,59.44 91.82,58.29 91.82,50.29
(copper drawn outside any net)
  shapes: Bottom circle x1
